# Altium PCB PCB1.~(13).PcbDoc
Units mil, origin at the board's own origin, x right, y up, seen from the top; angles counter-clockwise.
Board outline 3715 x 2925 mil, 2 copper layers (Top Layer, Bottom Layer); 4 components, 37 nets, 176 pads, 0 vias.
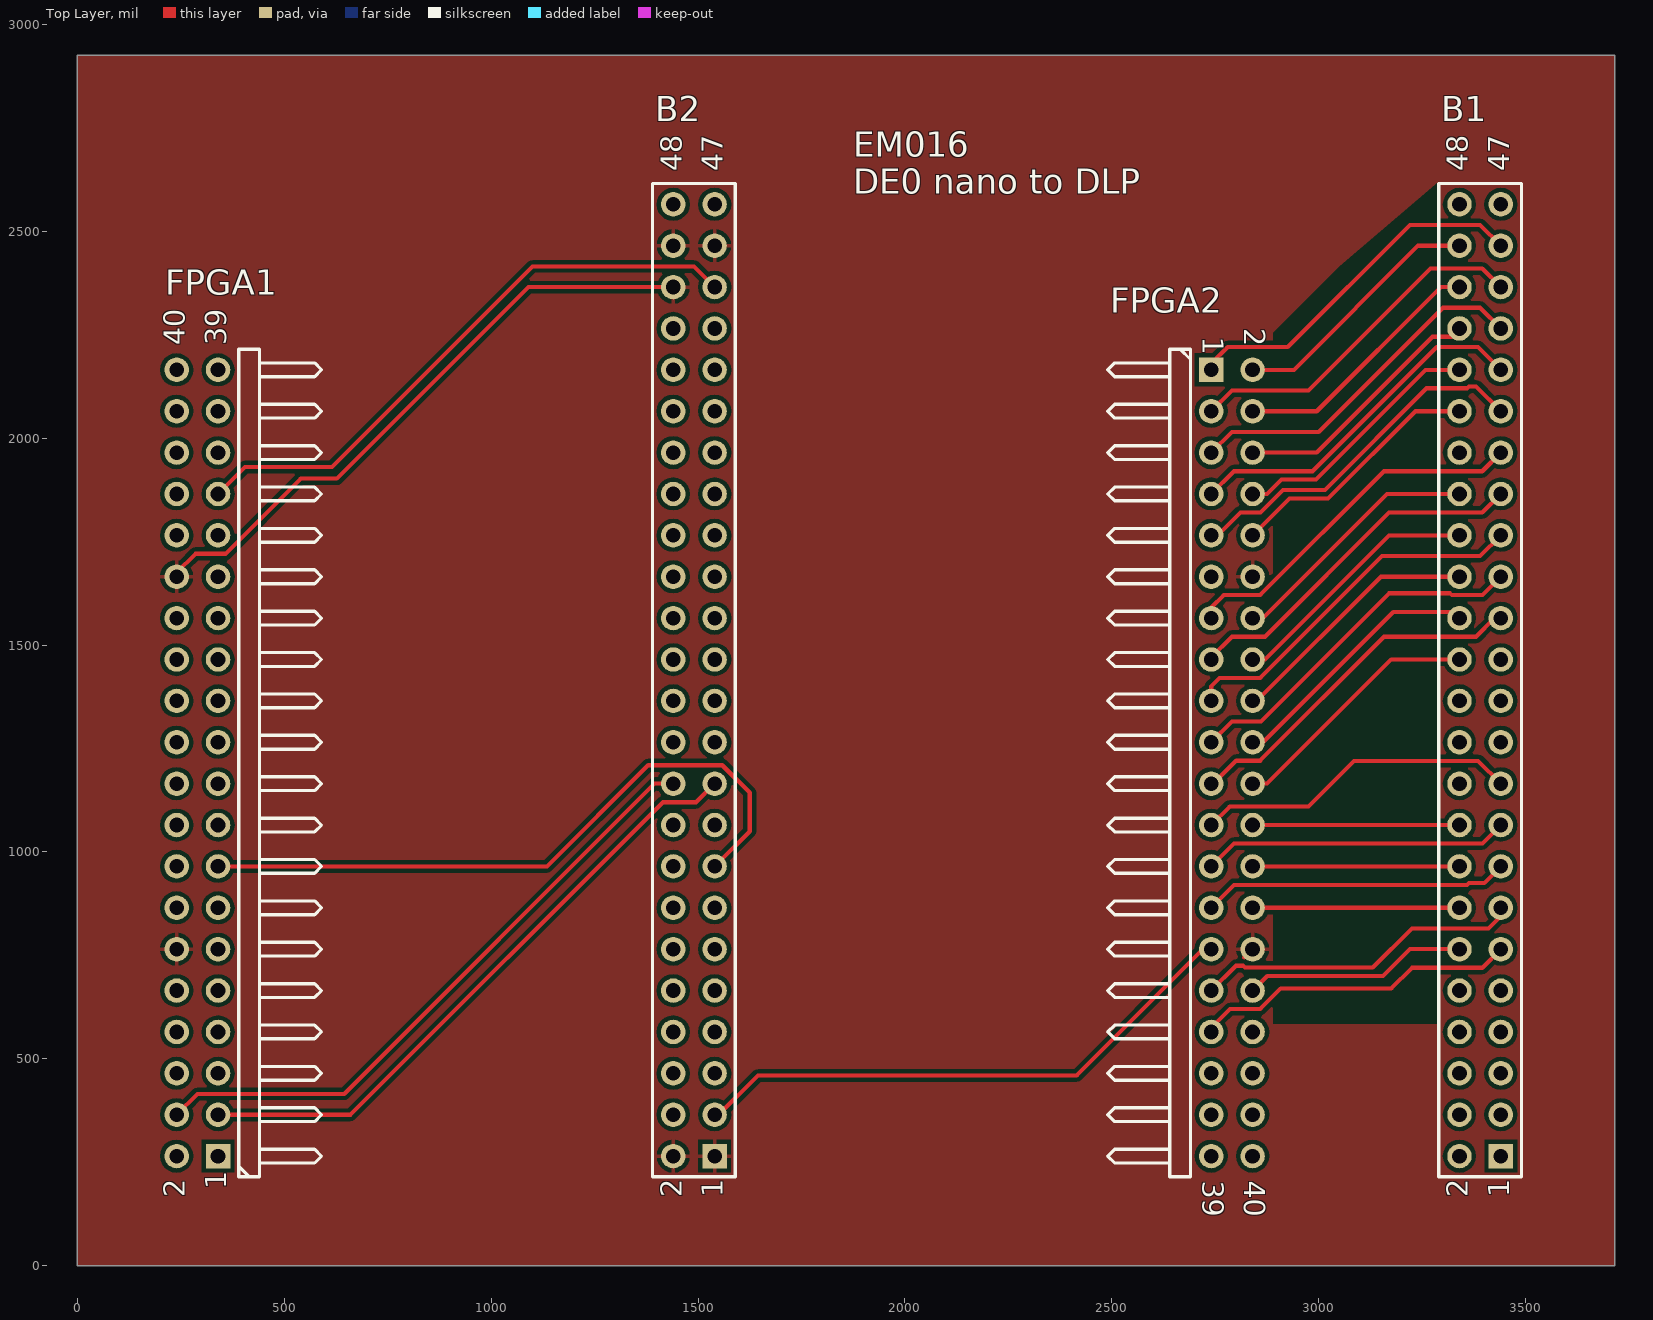
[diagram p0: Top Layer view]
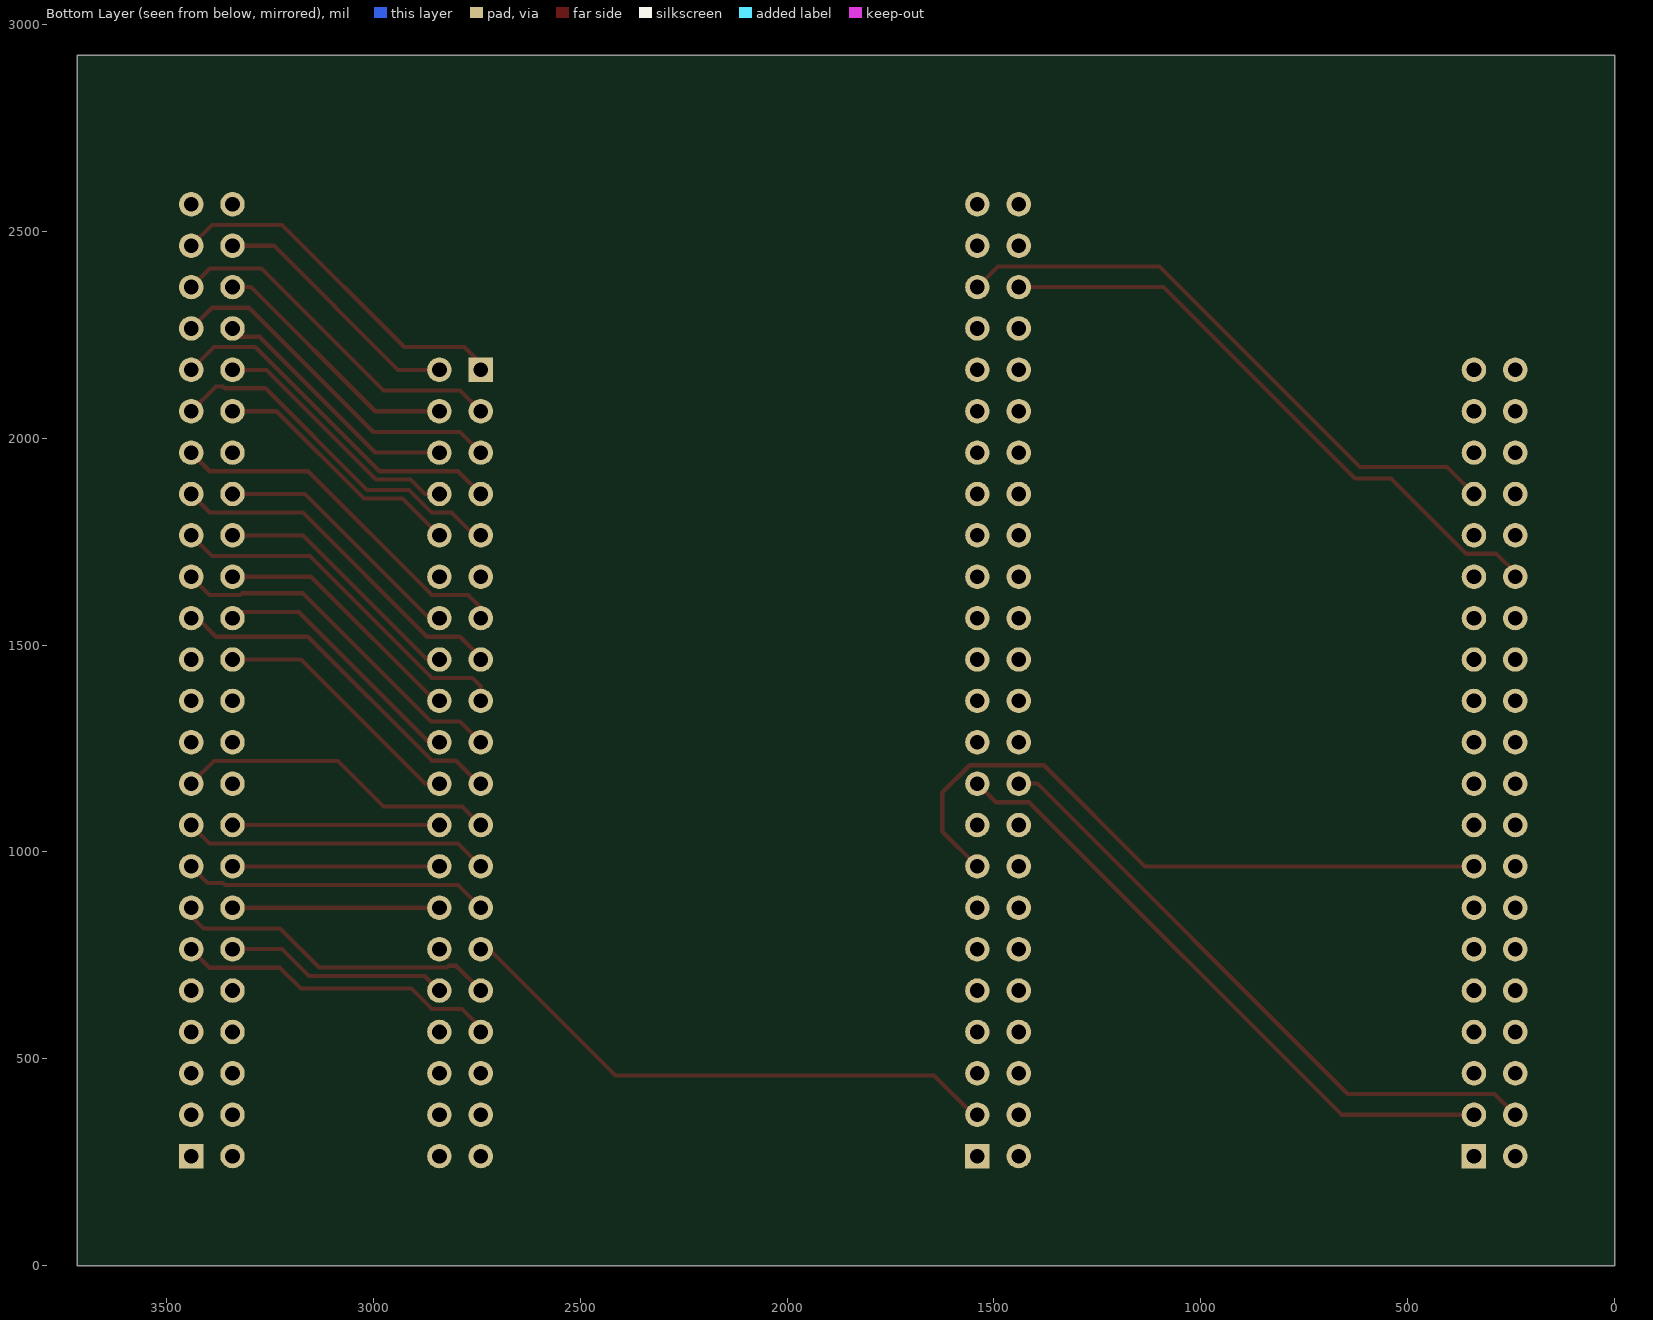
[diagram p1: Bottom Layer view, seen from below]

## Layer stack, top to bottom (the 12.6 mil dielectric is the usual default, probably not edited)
Top Solder: solder mask 0.4, Solder Resist, Dk 3.5
Top Layer: signal copper 1.4
Dielectric 1: dielectric 12.6, FR-4, Dk 4.8
Bottom Layer: signal copper 1.4
Bottom Solder: solder mask 0.4, Solder Resist, Dk 3.5

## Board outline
0,0 3715,0 3715,2925 0,2925

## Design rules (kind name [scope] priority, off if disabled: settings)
Clearance [All] p1: gap=10
PolygonConnect [All] p1: connectstyle=Relief reliefconductorwidth=10 reliefentries=4 polygonreliefangle="90 Angle" airgapwidth=10
RoomDefinition Sheet1 [InComponentClass('Sheet1')] p1 off: confinementstyle=ConfineIn formatcopy=TRUE lockcomponents=FALSE outline 6015,-870 7380,-870 7380,1825 6015,1825
RoutingVias [All] p1: holewidth=28 width=50 viastyle="Through Hole" minholewidth=28 minwidth=50 maxholewidth=28 maxwidth=50
SolderMaskExpansion [All] p1: expansion=4
Width [All] p1: maxlimit=10 minlimit=10 preferedwidth=10
30 further rules are at their usual default settings.

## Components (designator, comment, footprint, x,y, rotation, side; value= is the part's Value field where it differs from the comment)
B1 "Header 24X2" HDR2X24 3440,265 r90 top
B2 "Header 24X2" HDR2X24 1540,265 r90 top
FPGA1 "Header 20X2H" HDR2X20H 340,265 r90 top
FPGA2 "Header 20X2H" HDR2X20H 2740,2165 r270 top

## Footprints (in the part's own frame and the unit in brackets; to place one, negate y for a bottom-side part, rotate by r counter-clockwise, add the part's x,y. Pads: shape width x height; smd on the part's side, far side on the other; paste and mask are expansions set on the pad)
HDR2X20H [mm] "Connector; Header; 20x2 Position; Right Angle"
  rect 1.5x1.5 hole 0.9: 1(0,0)
  round 1.5 hole 0.9: 2(0,2.54) 3(2.54,0) 4(2.54,2.54) 5(5.08,0) 6(5.08,2.54) 7(7.62,0) 8(7.62,2.54) 9(10.16,0) 10(10.16,2.54) 11(12.7,0) 12(12.7,2.54) 13(15.24,0) 14(15.24,2.54) 15(17.78,0) 16(17.78,2.54) 17(20.32,0) 18(20.32,2.54) 19(22.86,0) 20(22.86,2.54) 21(25.4,0) 22(25.4,2.54) 23(27.94,0) 24(27.94,2.54) 25(30.48,0) 26(30.48,2.54) 27(33.02,0) 28(33.02,2.54) 29(35.56,0) 30(35.56,2.54) 31(38.1,0) 32(38.1,2.54) 33(40.64,0) 34(40.64,2.54) 35(43.18,0) 36(43.18,2.54) 37(45.72,0) 38(45.72,2.54) 39(48.26,0) 40(48.26,2.54)
  silkscreen extent -1.27,-6.35 49.53,-1.27
HDR2X24 [mm] "Connector; Header; 24x2 Position"
  rect 1.5x1.5 hole 0.9: 1(0,0)
  round 1.5 hole 0.9: 2(0,2.54) 3(2.54,0) 4(2.54,2.54) 5(5.08,0) 6(5.08,2.54) 7(7.62,0) 8(7.62,2.54) 9(10.16,0) 10(10.16,2.54) 11(12.7,0) 12(12.7,2.54) 13(15.24,0) 14(15.24,2.54) 15(17.78,0) 16(17.78,2.54) 17(20.32,0) 18(20.32,2.54) 19(22.86,0) 20(22.86,2.54) 21(25.4,0) 22(25.4,2.54) 23(27.94,0) 24(27.94,2.54) 25(30.48,0) 26(30.48,2.54) 27(33.02,0) 28(33.02,2.54) 29(35.56,0) 30(35.56,2.54) 31(38.1,0) 32(38.1,2.54) 33(40.64,0) 34(40.64,2.54) 35(43.18,0) 36(43.18,2.54) 37(45.72,0) 38(45.72,2.54) 39(48.26,0) 40(48.26,2.54) 41(50.8,0) 42(50.8,2.54) 43(53.34,0) 44(53.34,2.54) 45(55.88,0) 46(55.88,2.54) 47(58.42,0) 48(58.42,2.54)
  silkscreen extent -1.27,-1.27 59.69,3.81

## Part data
B1 B2: "Header, 24-Pin, Dual row"
FPGA1 FPGA2: "Header, 20-Pin, Dual row, Right Angle"

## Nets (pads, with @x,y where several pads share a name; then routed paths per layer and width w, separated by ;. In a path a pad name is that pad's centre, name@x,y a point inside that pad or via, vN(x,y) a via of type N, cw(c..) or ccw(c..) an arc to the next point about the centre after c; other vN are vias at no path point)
3.3V: B2.3 FPGA2.29 | length 1365.7
  Top Layer w10: B2.3 1550,365 1645,460 2415,460 2720,765 FPGA2.29
5V: FPGA2.11
DATA0: B1.45 FPGA2.1 | length 874.5
  Top Layer w10: FPGA2.1 2740,2180 2780,2220 2925,2220 3220,2515 3390,2515 B1.45
DATA1: B1.46 FPGA2.2 | length 624.3
  Top Layer w10: FPGA2.2 2940,2165 3240,2465 B1.46
DATA2: B1.43 FPGA2.3 | length 861.5
  Top Layer w10: FPGA2.3 2790,2115 2975,2115 3270,2410 3395,2410 B1.43
DATA3: B1.44 FPGA2.4 | length 624.3
  Top Layer w10: FPGA2.4 2995,2065 3295,2365 B1.44
DATA4: B1.41 FPGA2.5 | length 865.7
  Top Layer w10: FPGA2.5 2790,2015 3000,2015 3300,2315 3390,2315 B1.41
DATA5: B1.42 FPGA2.6 | length 624.3
  Top Layer w10: FPGA2.6 2995,1965 3275,2245 3320,2245 B1.42
DATA6: B1.39 FPGA2.7 | length 869.8
  Top Layer w10: FPGA2.7 2795,1920 2985,1920 3285,2220 3385,2220 B1.39
DATA7: B1.40 FPGA2.8 | length 624.3
  Top Layer w10: FPGA2.8 2875,1865 2910,1900 2993.28,1900 3258.28,2165 B1.40
DATA8: B1.37 FPGA2.9 | length 874
  Top Layer w10: FPGA2.9 2755,1765 2810.47,1820.47 2858.76,1820.47 2913.28,1875 3015,1875 3260.47,2120.47 3358.44,2120.47 3362.97,2125 3380,2125 B1.37
DATA9: B1.38 FPGA2.10 | length 624.3
  Top Layer w10: FPGA2.10 2929.22,1854.22 3022.5,1854.22 3233.28,2065 B1.38
DATA10: B1.36
DATA11: B1.34 FPGA2.14 | length 624.3
  Top Layer w10: FPGA2.14 2865,1565 3165,1865 B1.34
DATA12: B1.35 FPGA2.13 | length 880.3
  Top Layer w10: FPGA2.13 2740,1590 2770.47,1620.47 2858.44,1620.47 3157.97,1920 3395,1920 B1.35
DATA13: B1.33 FPGA2.15 | length 868.6
  Top Layer w10: FPGA2.15 2740,1470 2790,1520 2870,1520 3170,1820 3395,1820 B1.33
DATA14: B1.31 FPGA2.17 | length 886.2
  Top Layer w10: FPGA2.17 2740,1400 2760.47,1420.47 2858.44,1420.47 3152.97,1715 3390,1715 B1.31
DATA15: B1.32 FPGA2.16 | length 624.3
  Top Layer w10: FPGA2.16 2870,1465 3170,1765 B1.32
DATA16: B1.15 FPGA2.27 | length 741.4
  Top Layer w10: FPGA2.27 2795.47,920.47 3358.44,920.47 3362.97,925 3400,925 B1.15
DATA17: B1.16 FPGA2.26 | length 500
  Top Layer w10: FPGA2.26 B1.16
DATA18: B1.11 FPGA2.33 | length 788.7
  Top Layer w10: FPGA2.33 2740,575 2785.47,620.47 2858.44,620.47 2907.97,670 3175,670 3225,720 3395,720 B1.11
DATA19: B1.12 FPGA2.32 | length 541.4
  Top Layer w10: FPGA2.32 2875.47,700.47 3155.47,700.47 3220,765 B1.12
DATA20: B1.17 FPGA2.25 | length 741.4
  Top Layer w10: FPGA2.25 2795.47,1020.47 3395.47,1020.47 B1.17
DATA21: B1.14 FPGA2.28 | length 500
  Top Layer w10: FPGA2.28 B1.14
DATA22: B1.13 FPGA2.31 | length 798.3
  Top Layer w10: FPGA2.31 2800,725 2817.03,725 2821.56,720.47 3130.47,720.47 3225,815 3410,815 3440,845 B1.13
DATA23: B1.19 FPGA2.23 | length 787
  Top Layer w10: FPGA2.23 2785,1110 2975,1110 3085,1220 3385,1220 B1.19
DATAEN: B1.30 FPGA2.18 | length 624.3
  Top Layer w10: FPGA2.18 2850,1365 3150,1665 B1.30
EXT_SCL: B2.19 FPGA1.3 | length 1531.4
  Top Layer w10: FPGA1.3 660,365 1415,1120 1495,1120 B2.19
EXT_SDA: B2.20 FPGA1.4 | length 1531.4
  Top Layer w10: FPGA1.4 290,415 645,415 1395,1165 B2.20
GND: B2.1 B2.2 B2.44 B2.45 B2.46 FPGA1.12 FPGA1.30 FPGA2.12 FPGA2.30 | length 1524.1
  Top Layer w10: FPGA1.30 240,1675 285.47,1720.47 358.44,1720.47 540,1902.03 627.03,1902.03 1090,2365 B2.44 ; FPGA2.30@2820,745 FPGA2.30
GPIO5: B1.18 FPGA2.24 | length 500
  Top Layer w10: FPGA2.24 B1.18
GPIO_INIT_DONE: B1.26 FPGA2.22 | length 624.3
  Top Layer w10: FPGA2.22 2875,1165 3175,1465 B1.26
HOST_PRESENTZ: B2.43 FPGA1.33 | length 1448.5
  Top Layer w10: FPGA1.33 405,1930 615,1930 1100,2415 1490,2415 B2.43
HSYNC: B1.29 FPGA2.19 | length 869.4
  Top Layer w10: FPGA2.19 2790,1315 2860,1315 3170,1625 3317.03,1625 3321.56,1620.47 3395.47,1620.47 B1.29
PCLK: B1.28 FPGA2.20 | length 636.7
  Top Layer w10: FPGA2.20 2865,1265 3180,1580 3325,1580 B1.28
PROJ_ON_EXT: B2.15 FPGA1.15 | length 1627
  Top Layer w10: FPGA1.15 1135,965 1379.53,1209.53 1558.44,1209.53 1625,1142.97 1625,1050 B2.15
VSYNC: B1.27 FPGA2.21 | length 865.7
  Top Layer w10: FPGA2.21 2745,1165 2800.47,1220.47 2858.44,1220.47 3157.97,1520 3380,1520 3425,1565 B1.27
pads on no net: B1.1 B1.2 B1.3 B1.4 B1.5 B1.6 B1.7 B1.8 B1.9 B1.10 B1.20 B1.21 B1.22 B1.23 B1.24 B1.25 B1.47 B1.48 B2.4 B2.5 B2.6 B2.7 B2.8 B2.9 B2.10 B2.11 B2.12 B2.13 B2.14 B2.16 B2.17 B2.18 B2.21 B2.22 B2.23 B2.24 B2.25 B2.26 B2.27 B2.28 B2.29 B2.30 B2.31 B2.32 B2.33 B2.34 B2.35 B2.36 B2.37 B2.38 B2.39 B2.40 B2.41 B2.42 B2.47 B2.48 FPGA1.1 FPGA1.2 FPGA1.5 FPGA1.6 FPGA1.7 FPGA1.8 FPGA1.9 FPGA1.10 FPGA1.11 FPGA1.13 FPGA1.14 FPGA1.16 FPGA1.17 FPGA1.18 FPGA1.19 FPGA1.20 FPGA1.21 FPGA1.22 FPGA1.23 FPGA1.24 FPGA1.25 FPGA1.26 FPGA1.27 FPGA1.28 FPGA1.29 FPGA1.31 FPGA1.32 FPGA1.34 FPGA1.35 FPGA1.36 FPGA1.37 FPGA1.38 FPGA1.39 FPGA1.40 FPGA2.34 FPGA2.35 FPGA2.36 FPGA2.37 FPGA2.38 FPGA2.39 FPGA2.40

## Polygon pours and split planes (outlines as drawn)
GND on Top Layer "GND" (solid, pour order 2): 0,2925 0,0 3715,0 3715,2925 0,2925

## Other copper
Top Layer:
  pour cut-out: 2890,2254.68 3050.16,2414.84 3290,2619.93 3290,585 2890,585

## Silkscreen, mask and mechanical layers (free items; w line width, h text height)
Top Overlay:
  text "EM016 / DE0 nano to DLP" at 1875,2590 h60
